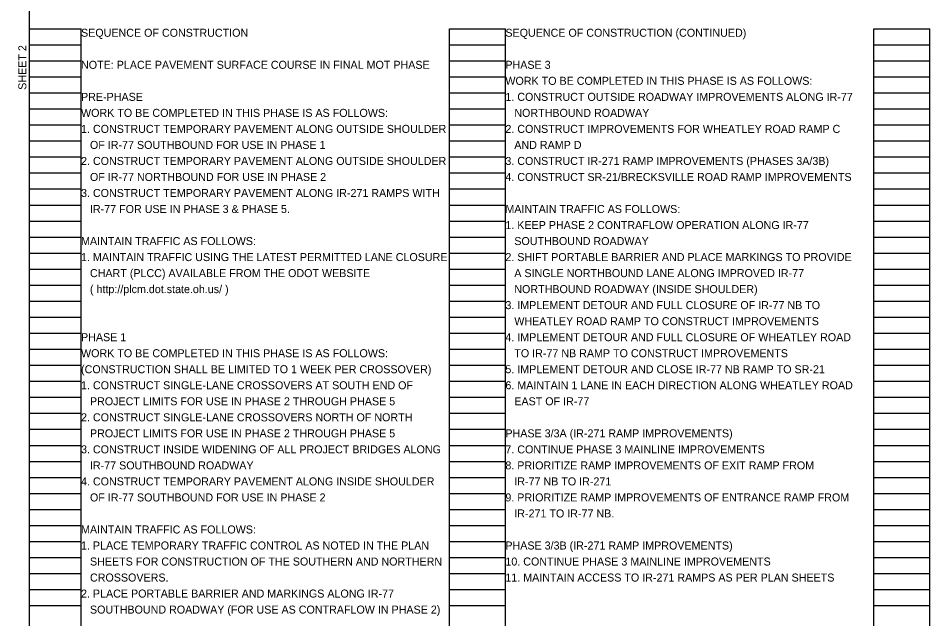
# Model space of a CAD drawing. Extents: x 1820207 to 1820557, y 740216 to 740315.
# Drawn here: x 1820261.19 to 1820277.13, y 740265.07 to 740275.57 of the extents above; entities that cross this region are included whole.
import ezdxf

# ---------------------------------------------------------------- set-up
doc = ezdxf.new("R2010")
doc.units = 0
for name, color, linetype in [('SC_Scratch1', 7, 'Continuous'), ('SC_Scratch2', 7, 'Continuous'), ('SH_Text', 7, 'Continuous')]:
    doc.layers.add(name, color=color, linetype=linetype)

msp = doc.modelspace()

# ---------------------------------------------------------------- linework, layer by layer
at = {"layer": 'SC_Scratch1'}
for p, q in [((1820261.39, 740255.222), (1820261.39, 740275.382)), ((1820261.39, 740275.382), (1820262.29, 740275.382)), ((1820262.29, 740255.222), (1820262.29, 740275.382)), ((1820268.73, 740255.222), (1820268.73, 740275.382)), ((1820268.73, 740275.382), (1820269.71, 740275.382)), ((1820269.71, 740255.222), (1820269.71, 740275.382)), ((1820276.15, 740255.222), (1820276.15, 740275.382)), ((1820276.15, 740275.382), (1820277.13, 740275.382)), ((1820277.13, 740255.222), (1820277.13, 740275.382)), ((1820261.39, 740275.102), (1820262.29, 740275.102)), ((1820268.73, 740275.102), (1820269.71, 740275.102)), ((1820276.15, 740275.102), (1820277.13, 740275.102)), ((1820261.39, 740274.822), (1820262.29, 740274.822)), ((1820268.73, 740274.822), (1820269.71, 740274.822)), ((1820276.15, 740274.822), (1820277.13, 740274.822)), ((1820261.39, 740274.542), (1820262.29, 740274.542)), ((1820268.73, 740274.542), (1820269.71, 740274.542)), ((1820276.15, 740274.542), (1820277.13, 740274.542)), ((1820261.39, 740274.262), (1820262.29, 740274.262)), ((1820268.73, 740274.262), (1820269.71, 740274.262)), ((1820276.15, 740274.262), (1820277.13, 740274.262)), ((1820261.39, 740273.982), (1820262.29, 740273.982)), ((1820268.73, 740273.982), (1820269.71, 740273.982)), ((1820276.15, 740273.982), (1820277.13, 740273.982)), ((1820261.39, 740273.702), (1820262.29, 740273.702)), ((1820268.73, 740273.702), (1820269.71, 740273.702)), ((1820276.15, 740273.702), (1820277.13, 740273.702)), ((1820261.39, 740273.422), (1820262.29, 740273.422)), ((1820268.73, 740273.422), (1820269.71, 740273.422)), ((1820276.15, 740273.422), (1820277.13, 740273.422)), ((1820261.39, 740273.142), (1820262.29, 740273.142)), ((1820268.73, 740273.142), (1820269.71, 740273.142)), ((1820276.15, 740273.142), (1820277.13, 740273.142)), ((1820261.39, 740272.862), (1820262.29, 740272.862)), ((1820268.73, 740272.862), (1820269.71, 740272.862)), ((1820276.15, 740272.862), (1820277.13, 740272.862)), ((1820261.39, 740272.582), (1820262.29, 740272.582)), ((1820268.73, 740272.582), (1820269.71, 740272.582)), ((1820276.15, 740272.582), (1820277.13, 740272.582)), ((1820261.39, 740272.302), (1820262.29, 740272.302)), ((1820268.73, 740272.302), (1820269.71, 740272.302)), ((1820276.15, 740272.302), (1820277.13, 740272.302)), ((1820261.39, 740272.022), (1820262.29, 740272.022)), ((1820268.73, 740272.022), (1820269.71, 740272.022)), ((1820276.15, 740272.022), (1820277.13, 740272.022)), ((1820261.39, 740271.742), (1820262.29, 740271.742)), ((1820268.73, 740271.742), (1820269.71, 740271.742)), ((1820276.15, 740271.742), (1820277.13, 740271.742)), ((1820261.39, 740271.462), (1820262.29, 740271.462)), ((1820268.73, 740271.462), (1820269.71, 740271.462)), ((1820276.15, 740271.462), (1820277.13, 740271.462)), ((1820261.39, 740271.182), (1820262.29, 740271.182)), ((1820268.73, 740271.182), (1820269.71, 740271.182)), ((1820276.15, 740271.182), (1820277.13, 740271.182)), ((1820261.39, 740270.902), (1820262.29, 740270.902)), ((1820268.73, 740270.902), (1820269.71, 740270.902)), ((1820276.15, 740270.902), (1820277.13, 740270.902)), ((1820261.39, 740270.622), (1820262.29, 740270.622)), ((1820268.73, 740270.622), (1820269.71, 740270.622)), ((1820276.15, 740270.622), (1820277.13, 740270.622)), ((1820261.39, 740270.342), (1820262.29, 740270.342)), ((1820268.73, 740270.342), (1820269.71, 740270.342)), ((1820276.15, 740270.342), (1820277.13, 740270.342)), ((1820261.39, 740270.062), (1820262.29, 740270.062)), ((1820268.73, 740270.062), (1820269.71, 740270.062)), ((1820276.15, 740270.062), (1820277.13, 740270.062)), ((1820261.39, 740269.782), (1820262.29, 740269.782)), ((1820268.73, 740269.782), (1820269.71, 740269.782)), ((1820276.15, 740269.782), (1820277.13, 740269.782)), ((1820261.39, 740269.502), (1820262.29, 740269.502)), ((1820268.73, 740269.502), (1820269.71, 740269.502)), ((1820276.15, 740269.502), (1820277.13, 740269.502)), ((1820261.39, 740269.222), (1820262.29, 740269.222)), ((1820268.73, 740269.222), (1820269.71, 740269.222)), ((1820276.15, 740269.222), (1820277.13, 740269.222)), ((1820261.39, 740268.942), (1820262.29, 740268.942)), ((1820268.73, 740268.942), (1820269.71, 740268.942)), ((1820276.15, 740268.942), (1820277.13, 740268.942)), ((1820261.39, 740268.662), (1820262.29, 740268.662)), ((1820268.73, 740268.662), (1820269.71, 740268.662)), ((1820276.15, 740268.662), (1820277.13, 740268.662)), ((1820261.39, 740268.382), (1820262.29, 740268.382)), ((1820268.73, 740268.382), (1820269.71, 740268.382)), ((1820276.15, 740268.382), (1820277.13, 740268.382)), ((1820261.39, 740268.102), (1820262.29, 740268.102)), ((1820268.73, 740268.102), (1820269.71, 740268.102)), ((1820276.15, 740268.102), (1820277.13, 740268.102)), ((1820261.39, 740267.822), (1820262.29, 740267.822)), ((1820268.73, 740267.822), (1820269.71, 740267.822)), ((1820276.15, 740267.822), (1820277.13, 740267.822)), ((1820261.39, 740267.542), (1820262.29, 740267.542)), ((1820268.73, 740267.542), (1820269.71, 740267.542)), ((1820276.15, 740267.542), (1820277.13, 740267.542)), ((1820261.39, 740267.262), (1820262.29, 740267.262)), ((1820268.73, 740267.262), (1820269.71, 740267.262)), ((1820276.15, 740267.262), (1820277.13, 740267.262)), ((1820261.39, 740266.982), (1820262.29, 740266.982)), ((1820268.73, 740266.982), (1820269.71, 740266.982)), ((1820276.15, 740266.982), (1820277.13, 740266.982)), ((1820261.39, 740266.702), (1820262.29, 740266.702)), ((1820268.73, 740266.702), (1820269.71, 740266.702)), ((1820276.15, 740266.702), (1820277.13, 740266.702)), ((1820261.39, 740266.422), (1820262.29, 740266.422)), ((1820268.73, 740266.422), (1820269.71, 740266.422)), ((1820276.15, 740266.422), (1820277.13, 740266.422)), ((1820261.39, 740266.142), (1820262.29, 740266.142)), ((1820268.73, 740266.142), (1820269.71, 740266.142)), ((1820276.15, 740266.142), (1820277.13, 740266.142)), ((1820261.39, 740265.862), (1820262.29, 740265.862)), ((1820268.73, 740265.862), (1820269.71, 740265.862)), ((1820276.15, 740265.862), (1820277.13, 740265.862)), ((1820261.39, 740265.582), (1820262.29, 740265.582)), ((1820268.73, 740265.582), (1820269.71, 740265.582)), ((1820276.15, 740265.582), (1820277.13, 740265.582)), ((1820261.39, 740265.302), (1820262.29, 740265.302)), ((1820268.73, 740265.302), (1820269.71, 740265.302)), ((1820276.15, 740265.302), (1820277.13, 740265.302))]:
    msp.add_line(p, q, dxfattribs=at)
at = {"layer": 'SC_Scratch2'}
msp.add_lwpolyline([(1820261.39, 740275.742), (1820291.89, 740275.742), (1820291.89, 740254.742), (1820261.39, 740254.742)], close=True, dxfattribs=at)

# ---------------------------------------------------------------- texts
at = {"layer": 'SH_Text'}
for s, rotation, p in [('SEQUENCE OF CONSTRUCTION', 360, (1820262.29, 740275.242)), ('SEQUENCE OF CONSTRUCTION (CONTINUED)', 360, (1820269.71, 740275.242)), ('SHEET 2', 90, (1820261.334, 740274.315)), ('NOTE: PLACE PAVEMENT SURFACE COURSE IN FINAL MOT PHASE', 360, (1820262.29, 740274.682)), ('PHASE 3', 360, (1820269.71, 740274.682)), ('WORK TO BE COMPLETED IN THIS PHASE IS AS FOLLOWS:', 360, (1820269.71, 740274.402)), ('PRE-PHASE', 360, (1820262.29, 740274.122)), ('1. CONSTRUCT OUTSIDE ROADWAY IMPROVEMENTS ALONG IR-77', 360, (1820269.71, 740274.122)), ('WORK TO BE COMPLETED IN THIS PHASE IS AS FOLLOWS:', 360, (1820262.29, 740273.842)), ('   NORTHBOUND ROADWAY', 360, (1820269.71, 740273.842)), ('1. CONSTRUCT TEMPORARY PAVEMENT ALONG OUTSIDE SHOULDER ', 360, (1820262.29, 740273.562)), ('2. CONSTRUCT IMPROVEMENTS FOR WHEATLEY ROAD RAMP C', 360, (1820269.71, 740273.562)), ('   OF IR-77 SOUTHBOUND FOR USE IN PHASE 1', 360, (1820262.29, 740273.282)), ('   AND RAMP D', 360, (1820269.71, 740273.282)), ('2. CONSTRUCT TEMPORARY PAVEMENT ALONG OUTSIDE SHOULDER', 360, (1820262.29, 740273.002)), ('3. CONSTRUCT IR-271 RAMP IMPROVEMENTS (PHASES 3A/3B)', 360, (1820269.71, 740273.002)), ('4. CONSTRUCT SR-21/BRECKSVILLE ROAD RAMP IMPROVEMENTS', 360, (1820269.71, 740272.722)), ('   OF IR-77 NORTHBOUND FOR USE IN PHASE 2', 360, (1820262.29, 740272.722)), ('3. CONSTRUCT TEMPORARY PAVEMENT ALONG IR-271 RAMPS WITH', 360, (1820262.29, 740272.442)), ('   IR-77 FOR USE IN PHASE 3 & PHASE 5.', 360, (1820262.29, 740272.162)), ('MAINTAIN TRAFFIC AS FOLLOWS:', 360, (1820269.71, 740272.162)), ('1. KEEP PHASE 2 CONTRAFLOW OPERATION ALONG IR-77 ', 360, (1820269.71, 740271.882)), ('MAINTAIN TRAFFIC AS FOLLOWS:', 360, (1820262.29, 740271.602)), ('   SOUTHBOUND ROADWAY', 360, (1820269.71, 740271.602)), ('1. MAINTAIN TRAFFIC USING THE LATEST PERMITTED LANE CLOSURE ', 360, (1820262.29, 740271.322)), ('2. SHIFT PORTABLE BARRIER AND PLACE MARKINGS TO PROVIDE ', 360, (1820269.71, 740271.322)), ('   CHART (PLCC) AVAILABLE FROM THE ODOT WEBSITE ', 360, (1820262.29, 740271.042)), ('   A SINGLE NORTHBOUND LANE ALONG IMPROVED IR-77 ', 360, (1820269.71, 740271.042)), ('   ( http://plcm.dot.state.oh.us/ )', 360, (1820262.29, 740270.762)), ('   NORTHBOUND ROADWAY (INSIDE SHOULDER)', 360, (1820269.71, 740270.762)), ('3. IMPLEMENT DETOUR AND FULL CLOSURE OF IR-77 NB TO ', 360, (1820269.71, 740270.482)), ('   WHEATLEY ROAD RAMP TO CONSTRUCT IMPROVEMENTS', 360, (1820269.71, 740270.202)), ('PHASE 1', 360, (1820262.29, 740269.922)), ('4. IMPLEMENT DETOUR AND FULL CLOSURE OF WHEATLEY ROAD ', 360, (1820269.71, 740269.922)), ('WORK TO BE COMPLETED IN THIS PHASE IS AS FOLLOWS:', 360, (1820262.29, 740269.642)), ('   TO IR-77 NB RAMP TO CONSTRUCT IMPROVEMENTS', 360, (1820269.71, 740269.642)), ('(CONSTRUCTION SHALL BE LIMITED TO 1 WEEK PER CROSSOVER)', 360, (1820262.29, 740269.362)), ('5. IMPLEMENT DETOUR AND CLOSE IR-77 NB RAMP TO SR-21', 360, (1820269.71, 740269.362)), ('1. CONSTRUCT SINGLE-LANE CROSSOVERS AT SOUTH END OF ', 360, (1820262.29, 740269.082)), ('6. MAINTAIN 1 LANE IN EACH DIRECTION ALONG WHEATLEY ROAD', 360, (1820269.71, 740269.082)), ('   PROJECT LIMITS FOR USE IN PHASE 2 THROUGH PHASE 5', 360, (1820262.29, 740268.802)), ('   EAST OF IR-77', 360, (1820269.71, 740268.802)), ('2. CONSTRUCT SINGLE-LANE CROSSOVERS NORTH OF NORTH', 360, (1820262.29, 740268.522)), ('   PROJECT LIMITS FOR USE IN PHASE 2 THROUGH PHASE 5', 360, (1820262.29, 740268.242)), ('PHASE 3/3A (IR-271 RAMP IMPROVEMENTS)', 360, (1820269.71, 740268.242)), ('3. CONSTRUCT INSIDE WIDENING OF ALL PROJECT BRIDGES ALONG ', 360, (1820262.29, 740267.962)), ('7. CONTINUE PHASE 3 MAINLINE IMPROVEMENTS', 360, (1820269.71, 740267.962)), ('   IR-77 SOUTHBOUND ROADWAY', 360, (1820262.29, 740267.682)), ('8. PRIORITIZE RAMP IMPROVEMENTS OF EXIT RAMP FROM ', 360, (1820269.71, 740267.682)), ('4. CONSTRUCT TEMPORARY PAVEMENT ALONG INSIDE SHOULDER ', 360, (1820262.29, 740267.402)), ('   IR-77 NB TO IR-271', 360, (1820269.71, 740267.402)), ('   OF IR-77 SOUTHBOUND FOR USE IN PHASE 2', 360, (1820262.29, 740267.122)), ('9. PRIORITIZE RAMP IMPROVEMENTS OF ENTRANCE RAMP FROM ', 360, (1820269.71, 740267.122)), ('   IR-271 TO IR-77 NB.', 360, (1820269.71, 740266.842)), ('MAINTAIN TRAFFIC AS FOLLOWS:', 360, (1820262.29, 740266.562)), ('1. PLACE TEMPORARY TRAFFIC CONTROL AS NOTED IN THE PLAN ', 360, (1820262.29, 740266.282)), ('PHASE 3/3B (IR-271 RAMP IMPROVEMENTS)', 360, (1820269.71, 740266.282)), ('   SHEETS FOR CONSTRUCTION OF THE SOUTHERN AND NORTHERN ', 360, (1820262.29, 740266.002)), ('10. CONTINUE PHASE 3 MAINLINE IMPROVEMENTS', 360, (1820269.71, 740266.002)), ('   CROSSOVERS.', 360, (1820262.29, 740265.722)), ('11. MAINTAIN ACCESS TO IR-271 RAMPS AS PER PLAN SHEETS', 360, (1820269.71, 740265.722)), ('2. PLACE PORTABLE BARRIER AND MARKINGS ALONG IR-77 ', 360, (1820262.29, 740265.442)), ('   SOUTHBOUND ROADWAY (FOR USE AS CONTRAFLOW IN PHASE 2)', 360, (1820262.29, 740265.162))]:
    msp.add_text(s, height=0.14, rotation=rotation, dxfattribs=at).set_placement(p)

doc.saveas('drawing.dxf')
